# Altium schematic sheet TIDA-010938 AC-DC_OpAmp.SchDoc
size 431 x 279 mm; Date: Not shown in title block; ApprovedBy: Not shown in title block; CheckedBy: Not shown in title block; Author: Not shown in title block; CompanyName: Not shown in title block; Engineer: Not shown in title block; Organization: Not shown in title block; Address1: Not shown in title block; Address2: Not shown in title block; Address3: Not shown in title block; Address4: Not shown in title block; DocumentNumber: 9; Revision: Use project parameter SCH_Rev; SheetNumber: 9; SheetTotal: 11; PageSetup: Record=PageOptions¦CenterHorizontal=True¦CenterVertical=True¦PrintScale=1.00¦XCorrection=1.00¦YCorrection=1.00¦PrintKind=0¦BorderSize=5000000¦LeftOffset=0¦BottomOffset=0¦Orientation=2¦PaperLength=1000¦PaperWidth=1000¦Scale=100¦PaperSource=15¦PrintQuality=600¦MediaType=1¦DitherType=10¦PaperKind=Letter¦PrintScaleMode=1
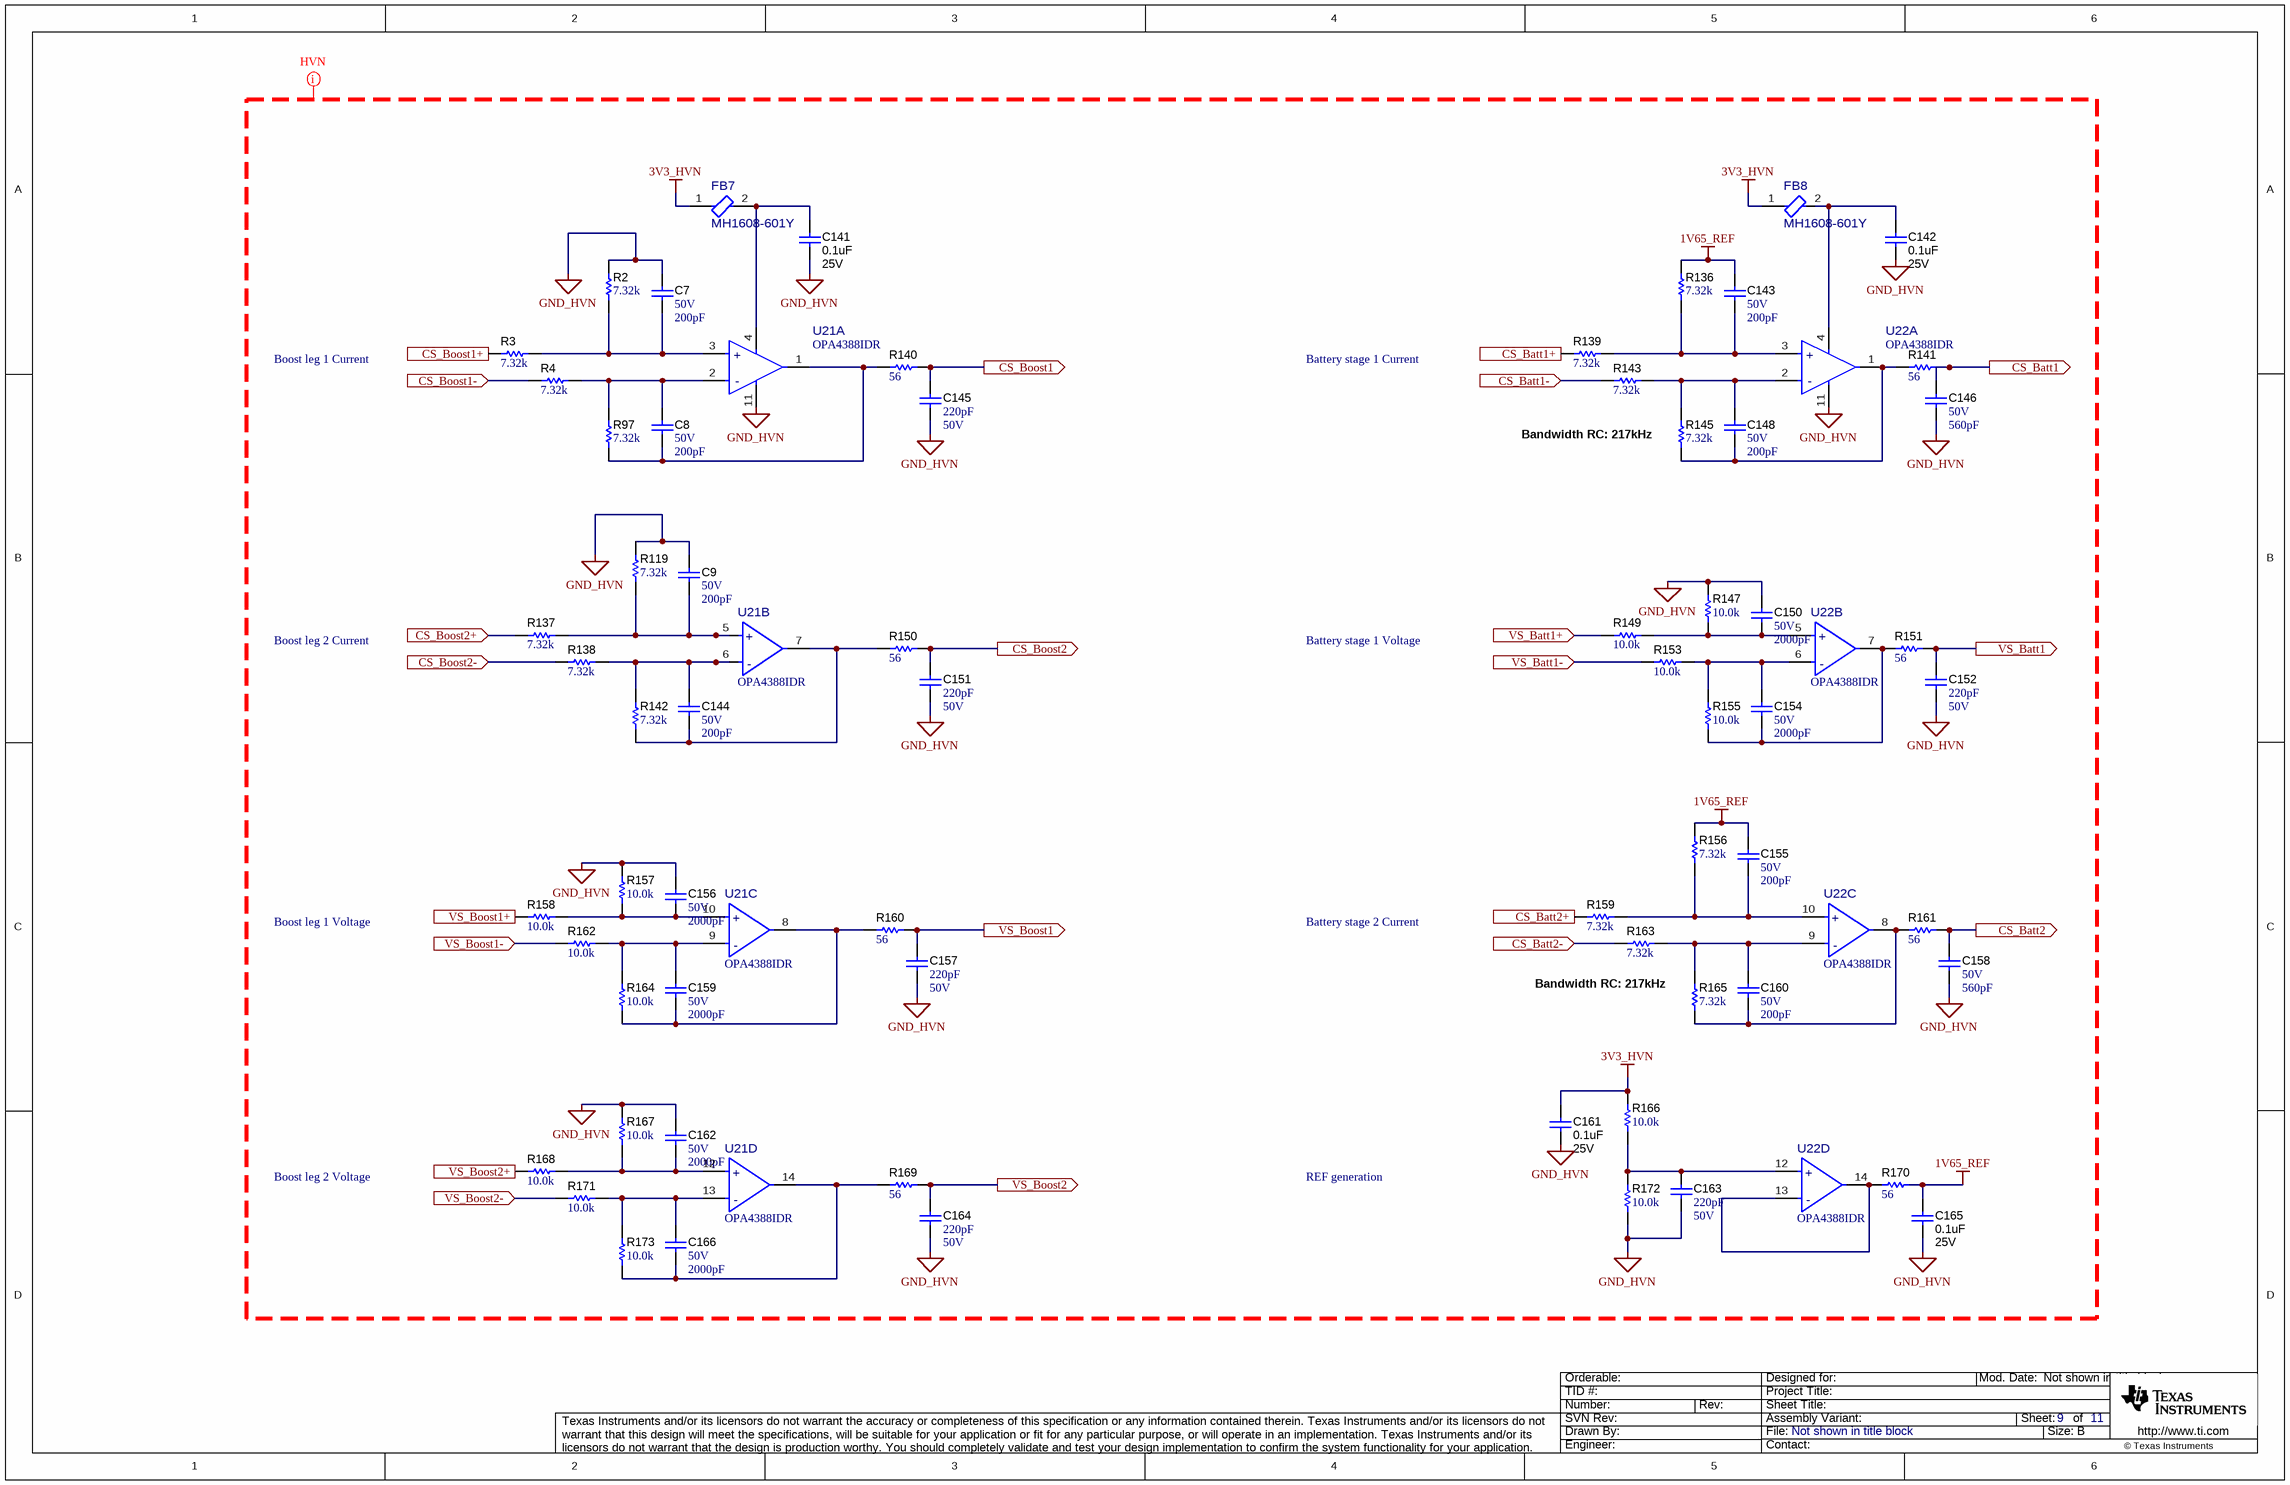
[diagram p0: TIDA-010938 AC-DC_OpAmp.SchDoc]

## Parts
C7  VDC_V: 50V  ValueDisplayed: 200pF  [0603]  (hidden comment: GRM1885C1H201JA01D)
C8  VDC_V: 50V  ValueDisplayed: 200pF  [0603]  (hidden comment: GRM1885C1H201JA01D)
C9  VDC_V: 50V  ValueDisplayed: 200pF  [0603]  (hidden comment: GRM1885C1H201JA01D)
C141  ValueDisplayed: 0.1uF  VDC_V: 25V  [0603]  (hidden comment: C0603X104K3RACTU)
C142  ValueDisplayed: 0.1uF  VDC_V: 25V  [0603]  (hidden comment: C0603X104K3RACTU)
C143  VDC_V: 50V  ValueDisplayed: 200pF  [0603]  (hidden comment: GRM1885C1H201JA01D)
C144  VDC_V: 50V  ValueDisplayed: 200pF  [0603]  (hidden comment: GRM1885C1H201JA01D)
C145  Cap_F: 220pF  VDC_V: 50V  [0603]  (hidden comment: GRM188R71H221KA01D)
C146  VDC_V: 50V  ValueDisplayed: 560pF  [0603]  (hidden comment: C0603C561J5GACTU)
C148  VDC_V: 50V  ValueDisplayed: 200pF  [0603]  (hidden comment: GRM1885C1H201JA01D)
C150  VDC_V: 50V  ValueDisplayed: 2000pF  [0603]  (hidden comment: GRM1885C1H202JA01D)
C151  Cap_F: 220pF  VDC_V: 50V  [0603]  (hidden comment: GRM188R71H221KA01D)
C152  Cap_F: 220pF  VDC_V: 50V  [0603]  (hidden comment: GRM188R71H221KA01D)
C154  VDC_V: 50V  ValueDisplayed: 2000pF  [0603]  (hidden comment: GRM1885C1H202JA01D)
C155  VDC_V: 50V  ValueDisplayed: 200pF  [0603]  (hidden comment: GRM1885C1H201JA01D)
C156  VDC_V: 50V  ValueDisplayed: 2000pF  [0603]  (hidden comment: GRM1885C1H202JA01D)
C157  Cap_F: 220pF  VDC_V: 50V  [0603]  (hidden comment: GRM188R71H221KA01D)
C158  VDC_V: 50V  ValueDisplayed: 560pF  [0603]  (hidden comment: C0603C561J5GACTU)
C159  VDC_V: 50V  ValueDisplayed: 2000pF  [0603]  (hidden comment: GRM1885C1H202JA01D)
C160  VDC_V: 50V  ValueDisplayed: 200pF  [0603]  (hidden comment: GRM1885C1H201JA01D)
C161  ValueDisplayed: 0.1uF  VDC_V: 25V  [0603]  (hidden comment: C0603X104K3RACTU)
C162  VDC_V: 50V  ValueDisplayed: 2000pF  [0603]  (hidden comment: GRM1885C1H202JA01D)
C163  Cap_F: 220pF  VDC_V: 50V  [0603]  (hidden comment: GRM188R71H221KA01D)
C164  Cap_F: 220pF  VDC_V: 50V  [0603]  (hidden comment: GRM188R71H221KA01D)
C165  ValueDisplayed: 0.1uF  VDC_V: 25V  [0603]  (hidden comment: C0603X104K3RACTU)
C166  VDC_V: 50V  ValueDisplayed: 2000pF  [0603]  (hidden comment: GRM1885C1H202JA01D)
FB7  MH1608-601Y  [FP-MH1608-601Y_0603-MFG]
FB8  MH1608-601Y  [FP-MH1608-601Y_0603-MFG]
R2  ValueDisplayed: 7.32k  [0603]  (hidden comment: RT0603BRD077K32L)
R3  ValueDisplayed: 7.32k  [0603]  (hidden comment: RT0603BRD077K32L)
R4  ValueDisplayed: 7.32k  [0603]  (hidden comment: RT0603BRD077K32L)
R97  ValueDisplayed: 7.32k  [0603]  (hidden comment: RT0603BRD077K32L)
R119  ValueDisplayed: 7.32k  [0603]  (hidden comment: RT0603BRD077K32L)
R136  ValueDisplayed: 7.32k  [0603]  (hidden comment: RT0603BRD077K32L)
R137  ValueDisplayed: 7.32k  [0603]  (hidden comment: RT0603BRD077K32L)
R138  ValueDisplayed: 7.32k  [0603]  (hidden comment: RT0603BRD077K32L)
R139  ValueDisplayed: 7.32k  [0603]  (hidden comment: RT0603BRD077K32L)
R140  ValueDisplayed: 56  [0603]  (hidden comment: RG1608P-560-B-T5)
R141  ValueDisplayed: 56  [0603]  (hidden comment: RG1608P-560-B-T5)
R142  ValueDisplayed: 7.32k  [0603]  (hidden comment: RT0603BRD077K32L)
R143  ValueDisplayed: 7.32k  [0603]  (hidden comment: RT0603BRD077K32L)
R145  ValueDisplayed: 7.32k  [0603]  (hidden comment: RT0603BRD077K32L)
R147  ValueDisplayed: 10.0k  [0603]  (hidden comment: RG1608P-103-B-T5)
R149  ValueDisplayed: 10.0k  [0603]  (hidden comment: RG1608P-103-B-T5)
R150  ValueDisplayed: 56  [0603]  (hidden comment: RG1608P-560-B-T5)
R151  ValueDisplayed: 56  [0603]  (hidden comment: RG1608P-560-B-T5)
R153  ValueDisplayed: 10.0k  [0603]  (hidden comment: RG1608P-103-B-T5)
R155  ValueDisplayed: 10.0k  [0603]  (hidden comment: RG1608P-103-B-T5)
R156  ValueDisplayed: 7.32k  [0603]  (hidden comment: RT0603BRD077K32L)
R157  ValueDisplayed: 10.0k  [0603]  (hidden comment: RG1608P-103-B-T5)
R158  ValueDisplayed: 10.0k  [0603]  (hidden comment: RG1608P-103-B-T5)
R159  ValueDisplayed: 7.32k  [0603]  (hidden comment: RT0603BRD077K32L)
R160  ValueDisplayed: 56  [0603]  (hidden comment: RG1608P-560-B-T5)
R161  ValueDisplayed: 56  [0603]  (hidden comment: RG1608P-560-B-T5)
R162  ValueDisplayed: 10.0k  [0603]  (hidden comment: RG1608P-103-B-T5)
R163  ValueDisplayed: 7.32k  [0603]  (hidden comment: RT0603BRD077K32L)
R164  ValueDisplayed: 10.0k  [0603]  (hidden comment: RG1608P-103-B-T5)
R165  ValueDisplayed: 7.32k  [0603]  (hidden comment: RT0603BRD077K32L)
R166  ValueDisplayed: 10.0k  [0603]  (hidden comment: RG1608P-103-B-T5)
R167  ValueDisplayed: 10.0k  [0603]  (hidden comment: RG1608P-103-B-T5)
R168  ValueDisplayed: 10.0k  [0603]  (hidden comment: RG1608P-103-B-T5)
R169  ValueDisplayed: 56  [0603]  (hidden comment: RG1608P-560-B-T5)
R170  ValueDisplayed: 56  [0603]  (hidden comment: RG1608P-560-B-T5)
R171  ValueDisplayed: 10.0k  [0603]  (hidden comment: RG1608P-103-B-T5)
R172  ValueDisplayed: 10.0k  [0603]  (hidden comment: RG1608P-103-B-T5)
R173  ValueDisplayed: 10.0k  [0603]  (hidden comment: RG1608P-103-B-T5)
U21  OPA4388IDR  [D0014A-MFG]  (parts A,B,C,D of 4)
U22  OPA4388IDR  [D0014A-MFG]  (parts A,B,C,D of 4)

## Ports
CS_Batt1 (out), CS_Batt1+ (in), CS_Batt1- (in), CS_Batt2 (out), CS_Batt2+ (in), CS_Batt2- (in), CS_Boost1 (out), CS_Boost1+ (in), CS_Boost1- (in), CS_Boost2 (out), CS_Boost2+ (in), CS_Boost2- (in), VS_Batt1 (out), VS_Batt1+ (in), VS_Batt1- (in), VS_Boost1 (out), VS_Boost1+ (in), VS_Boost1- (in), VS_Boost2 (out), VS_Boost2+ (in), VS_Boost2- (in)

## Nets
1V65_REF: C143.1 C155.1 C165.2 R136.2 R156.2 R170.2
3V3_HVN: C161.2 FB7.1 FB8.1 R166.1
GND_HVN: C7.1 C9.1 C141.1 C142.1 C145.1 C146.2 C150.2 C151.1 C152.1 C156.2 C157.1 C158.2 C161.1 C162.2 C163.1 C164.1 C165.1 R2.2 R119.2 R147.1 R157.1 R167.1 R172.2 U21.11(V-) U22.11(V-)
CS_Batt1: C146.1 R141.2 ; port CS_Batt1
CS_Batt1+: R139.1 ; port CS_Batt1+
CS_Batt1-: R143.1 ; port CS_Batt1-
CS_Batt2: C158.1 R161.2 ; port CS_Batt2
CS_Batt2+: R159.1 ; port CS_Batt2+
CS_Batt2-: R163.1 ; port CS_Batt2-
CS_Boost1: C145.2 R140.2 ; port CS_Boost1
CS_Boost1+: R3.1 ; port CS_Boost1+
CS_Boost1-: R4.1 ; port CS_Boost1-
CS_Boost2: C151.2 R150.2 ; port CS_Boost2
CS_Boost2+: R137.1 ; port CS_Boost2+
CS_Boost2-: R138.1 ; port CS_Boost2-
VS_Batt1: C152.2 R151.2 ; port VS_Batt1
VS_Batt1+: R149.2 ; port VS_Batt1+
VS_Batt1-: R153.2 ; port VS_Batt1-
VS_Boost1: C157.2 R160.2 ; port VS_Boost1
VS_Boost1+: R158.2 ; port VS_Boost1+
VS_Boost1-: R162.2 ; port VS_Boost1-
VS_Boost2: C164.2 R169.2 ; port VS_Boost2
VS_Boost2+: R168.2 ; port VS_Boost2+
VS_Boost2-: R171.2 ; port VS_Boost2-
NetC7_2: C7.2 R2.1 R3.2 U21.3(+IN_A)
NetC8_1: C8.1 R4.2 R97.2 U21.2(-IN_A)
NetC8_2: C8.2 R97.1 R140.1 U21.1(OUT_A)
NetC9_2: C9.2 R119.1 R137.2 U21.5(+IN_B)
NetC141_2: C141.2 FB7.2 U21.4(V+)
NetC142_2: C142.2 FB8.2 U22.4(V+)
NetC143_2: C143.2 R136.1 R139.2 U22.3(+IN_A)
NetC144_1: C144.1 R138.2 R142.2 U21.6(-IN_B)
NetC144_2: C144.2 R142.1 R150.1 U21.7(OUT_B)
NetC148_1: C148.1 R143.2 R145.2 U22.2(-IN_A)
NetC148_2: C148.2 R141.1 R145.1 U22.1(OUT_A)
NetC150_1: C150.1 R147.2 R149.1 U22.5(+IN_B)
NetC154_1: C154.1 R153.1 R155.1 U22.6(-IN_B)
NetC154_2: C154.2 R151.1 R155.2 U22.7(OUT_B)
NetC155_2: C155.2 R156.1 R159.2 U22.10(+IN_C)
NetC156_1: C156.1 R157.2 R158.1 U21.10(+IN_C)
NetC159_1: C159.1 R162.1 R164.1 U21.9(-IN_C)
NetC159_2: C159.2 R160.1 R164.2 U21.8(OUT_C)
NetC160_1: C160.1 R163.2 R165.2 U22.9(-IN_C)
NetC160_2: C160.2 R161.1 R165.1 U22.8(OUT_C)
NetC162_1: C162.1 R167.2 R168.1 U21.12(+IN_D)
NetC163_2: C163.2 R166.2 R172.1 U22.12(+IN_D)
NetC166_1: C166.1 R171.1 R173.1 U21.13(-IN_D)
NetC166_2: C166.2 R169.1 R173.2 U21.14(OUT_D)
NetR170_1: R170.1 U22.13(-IN_D) U22.14(OUT_D)

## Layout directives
net class HVN: 1V65_REF, 3V3_HVN, GND_HVN

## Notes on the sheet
- Boost leg 1 Current
- Battery stage 1 Current
- Bandwidth RC: 217kHz
- Boost leg 2 Current
- Battery stage 1 Voltage
- Boost leg 1 Voltage
- Battery stage 2 Current
- Boost leg 2 Voltage
- REF generation

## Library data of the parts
C7-C9 C143 C144 C148 C155 C160 = CMP-0007194-4: CAP, CERM, 200 pF, 50 V, +/- 5%, C0G/NP0, 0603; Manufacturer: MuRata; TaMin_C: -55°C; Polarized: N; SizeAreaWB_mm2: 4.68; Value1: Unknown; U/M: EA; Value: 200pF; TaMax_C: 125°C; SizeZ_mm: 1; SizeX_mm: 1.6; SizeY_mm: 0.8; SizeArea_mm2: 1.28; AEC Category: Q200
C141 C142 C161 C165 = CMP-0006979-5: CAP, CERM, 0.1 uF, 25 V, +/- 10%, X7R, 0603; Manufacturer: Kemet; Polarized: N; Value: 0.1uF; U/M: EA; Cap_F: 100nF; Value1: Unknown; TaMin_C: -55°C; TaMax_C: 125°C; AEC Category: Q200; SizeArea_mm2: 1.28; SizeAreaWB_mm2: 4.68; SizeX_mm: 1.6; SizeY_mm: 0.8; SizeZ_mm: 1
C145 C151 C152 C157 C163 C164 = CMP-0007442-5: CAP, CERM, 220 pF, 50 V, +/- 10%, X7R, 0603; Manufacturer: MuRata; TaMin_C: -55°C; Polarized: N; SizeAreaWB_mm2: 4.68; Value1: Unknown; U/M: EA; Value: 220pF; TaMax_C: 125°C; SizeZ_mm: 1; SizeX_mm: 1.6; SizeY_mm: 0.8; SizeArea_mm2: 1.28; AEC Category: Q200
C146 C158 = CMP-0006953-4: CAP, CERM, 560 pF, 50 V, +/- 5%, C0G/NP0, 0603; Manufacturer: Kemet; TaMin_C: -55°C; Polarized: N; SizeAreaWB_mm2: 4.68; Value1: Unknown; U/M: EA; Value: 560pF; TaMax_C: 125°C; SizeZ_mm: 1; SizeX_mm: 1.6; SizeY_mm: 0.8; SizeArea_mm2: 1.28; AEC Category: Q200
C150 C154 C156 C159 C162 C166 = CMP-0007195-4: CAP, CERM, 2000 pF, 50 V, +/- 5%, C0G/NP0, 0603; Manufacturer: MuRata; TaMin_C: -55°C; Polarized: N; SizeAreaWB_mm2: 4.68; Value1: Unknown; U/M: EA; Value: 2000pF; TaMax_C: 125°C; SizeZ_mm: 1; SizeX_mm: 1.6; SizeY_mm: 0.8; SizeArea_mm2: 1.28; Cap_F: 2nF; AEC Category: Q200
FB7 FB8 = CMP-0037505-1: 600 Ohms @ 100 MHz 1 Power, Signal Line Ferrite Bead 0603 (1608 Metric) 1A 200mOhm; Manufacturer: Bourns; DCR_ohm: 0.2; SizeZ_mm: 1mm; AEC Qualified: No; Impedance At Frequency: 600Ω @ 100MHz; Test Frequency: 100MHz; Tolerance_%: 25%
R2-R4 R97 R119 R136-R139 R142 R143 R145 R156 R159 R163 R165 = CMP-0024479-2: RES, 7.32 k, 0.1%, 0.1 W, 0603; Manufacturer: Yageo America; Power_W: 100mW; TempCo: 25 ppm/C; Value_Code: 7k32; U/M: EA; Value: 7.32k; EIA_Code: E192; SizeX_mm: 1.6; SizeY_mm: 0.8; SizeZ_mm: 1; Value2: 0.1W; SizeArea_mm2: 1.28; VDC_V: 75V; AEC Category: Q200
R140 R141 R150 R151 R160 R161 R169 R170 = CMP-0023572-3: RES, 56, 0.1%, 0.1 W, 0603; Manufacturer: Susumu Co Ltd; Power_W: 100mW; TempCo: 25 ppm/C; Value_Code: 56R0; U/M: EA; Value: 56; SizeX_mm: 1.6; SizeY_mm: 0.8; SizeZ_mm: 1; Value2: 0.1W; SizeArea_mm2: 1.28; VDC_V: 75V; AEC Category: Q200
R147 R149 R153 R155 R157 R158 R162 R164 R166-R168 R171-R173 = CMP-0023404-3: RES, 10.0 k, 0.1%, 0.1 W, 0603; Manufacturer: Susumu Co Ltd; Power_W: 100mW; TempCo: 25 ppm/C; Value_Code: 10k0; U/M: EA; Value: 10.0k; EIA_Code: E192; Res_ohm: 10k; SizeX_mm: 1.6; SizeY_mm: 0.8; SizeZ_mm: 1; Value2: 0.1W; SizeArea_mm2: 1.28; VDC_V: 75V; AEC Category: Q200
U21 U22 = CMP-0097120-1: Op Amp Quad Zero Drift Amplifier R-R I/O ±2.75V/5.5V 14-Pin SOIC T/R; Manufacturer: Texas Instruments; Standoff Height: 0.1mm; SizeZ_mm: 1.75mm; Number Of Channels: 4; Max Dual Supply Voltage: 2.75V; Input Bias Current: 0.00003uA; TaMin_C: -55°C; TaMax_C: +150°C; Input Offset Voltage: 0.00225mV; Min Dual Supply Voltage: 1.25V; Output Current Per Channel: 60mA; Response Time: 2us; Gain Bandwidth: 10MHz; Max Supply Voltage: 5.5V; Voltage Gain: 148dB; AEC Qualified: No; Nominal Supply Current: 1.7-1.9mA; Min Supply Voltage: 2.5V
